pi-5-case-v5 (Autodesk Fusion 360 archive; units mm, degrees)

design "Pi 5 case" references "M3x5x4 heat-Insert"
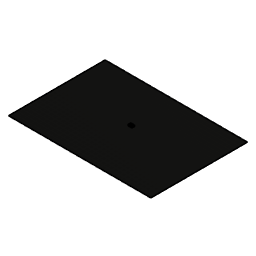
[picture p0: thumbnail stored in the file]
description: arrangementsContainer
description: STEP AP203
part number: RP-004882-DD - Pi 5 Mechanical Reference 3D model Iss1
description: Part Number
part number: PCB_for REF 060923
part number: GPIO Header for REF
part number: Micro HDMI for REF
part number: SD CARD for REF
part number: USB-C for REF
parameter "d2_1" = 180
parameter "d222_1" = 5
parameter "d223_1" = 5.3
parameter "d225_1" = 2
parameter "d226_1" = 10
parameter "d227_1" = 25
parameter "d228_1" = 20
parameter "d240_1" = 5
parameter "d241_1" = 5.3
parameter "d243_1" = 2
parameter "d244_1" = 10
parameter "d245_1" = 20
parameter "d246_1" = 25
parameter "d249_1" = 30
parameter "d250_1" = 0
parameter "d253_1" = 30
parameter "d254_1" = 0
parameter "d3" = 180
parameter "d4" = 0
parameter "d6" = 5
parameter "d7" = 5
parameter "d8" = 0
parameter "d10" = 24.193
parameter "d12" = 20.9455
parameter "d14" = 28.705
parameter "d16" = 27.166
parameter "d18" = 29.088
parameter "d20" = -25
parameter "d21" = 20.935
parameter "d23" = -3
parameter "d27" = 6
parameter "d28" = 0
parameter "d29" = 2
parameter "d30" = 2
parameter "d31" = 10
parameter "d32" = 2
parameter "d34" = 3
parameter "d35" = 20
parameter "d38" = 60
parameter "d39" = 0
parameter "d40" = -5
parameter "d42" = -3.933
parameter "d43" = -1
parameter "d44" = -3
parameter "d45" = 1
parameter "d46" = 1
parameter "d47" = 0
parameter "d48" = 5
parameter "d49" = -11.7
parameter "d51" = 3
parameter "d52" = -1.4
parameter "d53" = 3
parameter "d55" = 2
parameter "d56" = 1.4
parameter "d57" = -1
parameter "d58" = 1
parameter "d59" = -1
parameter "d60" = -0.4
parameter "d61" = -0.4
parameter "d62" = -1.053
parameter "d63" = -2
parameter "d65" = 0.172
parameter "d66" = -5
parameter "d67" = -2
parameter "d68" = -1
parameter "d69" = 2.5
parameter "d70" = -1
parameter "d71" = 0.4
parameter "d72" = 15
parameter "d74" = 0.1
parameter "d75" = 2
parameter "d76" = 0.75
parameter "d77" = 1
parameter "d79" = -1
parameter "d80" = 1
parameter "d83" = 0.75
parameter "d84" = 0.75
parameter "d85" = 0.8
parameter "d86" = 0.75
parameter "d87" = 0.75
parameter "d88" = 0.75
parameter "d89" = 0.75
parameter "d90" = 45 (= "Angle1")
parameter "d91" = 0 (= "Angle2")
parameter "d92" = 0.2
parameter "d93" = -0.2
parameter "d94" = -0.1
parameter "d95" = 2
parameter "d96" = 2
parameter "d97" = 15
parameter "d98" = 2
parameter "d101" = 0.6
parameter "d102" = 2.6
parameter "d103" = -0.1
parameter "d104" = 2
parameter "d105" = -0.1
parameter "d106" = -0.1
parameter "d107" = -0.1
parameter "d108" = 25
parameter "d109" = 2.6
parameter "d111" = 2.5
parameter "d112" = -0.1
parameter "d113" = 5
parameter "d114" = -3
parameter "d116" = 0.5
parameter "d117" = 7
parameter "d118" = 2
parameter "d119" = 5
parameter "d121" = -1
parameter "d122" = -2
parameter "d124" = 0.5
parameter "d128" = 2
parameter "d131" = 0.4
parameter "d132" = 0.5
parameter "d133" = 1
parameter "d134" = 3
parameter "d135" = 2.8
parameter "d137" = 3
parameter "d138" = 2.8
parameter "d140" = 7.375
parameter "d141" = 2
parameter "d143" = 2.8
parameter "d144" = 2.8
parameter "d145" = 5
parameter "d146" = 2.8
parameter "d147" = -0.4
parameter "d149" = -0.2
parameter "d151" = 0.4
parameter "d152" = 0.3
parameter "d153" = 0.4
parameter "d155" = -0.2
parameter "d156" = -0.2
parameter "d157" = 0.399
parameter "d159" = 5
parameter "d161" = 45 (= "Angle1")
parameter "d162" = 0 (= "Angle2")
parameter "d163" = 45 (= "Angle1")
parameter "d164" = 0 (= "Angle2")
parameter "d165" = 2.5
parameter "d166" = 3
parameter "d167" = 3
parameter "d168" = 2.5
parameter "d169" = 1
parameter "d170" = 1
parameter "d171" = 1
parameter "d172" = 3
parameter "d173" = 1
parameter "d174" = 1
parameter "d176" = 40.1
parameter "d177" = 40.1
parameter "d178" = -4.3752
parameter "d180" = 1.1
parameter "d181" = -4.3752
parameter "d183" = -0.1
parameter "d184" = 1
parameter "d185" = -2.291
parameter "d187" = 4
parameter "d188" = -1.625
parameter "d190" = 0
parameter "d191" = 10.23
parameter "d193" = 10
parameter "d194" = 2
parameter "d196" = 10
parameter "d197" = 2
parameter "d199" = 10
parameter "d200" = 2
parameter "d202" = 10
parameter "d203" = 2
parameter "d205" = 1
parameter "d206" = 0.4
parameter "d207" = 0.4
parameter "d208" = 8
parameter "d212" = 10
parameter "d213" = 3.3
parameter "d215" = -2
parameter "d217" = 0.5
parameter "d218" = 0.3
parameter "d219" = 0.3
parameter "d220" = 2
parameter "d221" = 3
parameter "d222" = 0.2
parameter "d224" = 0.5
parameter "d225" = 0.8
parameter "d226" = -0.8
parameter "d227" = 10
parameter "d229" = 2.5
parameter "d231" = 0.5
parameter "d232" = 2.5
parameter "d233" = 2
parameter "d238" = 5
parameter "d239" = -8
parameter "d241" = 0.5
parameter "d242" = -3.536
parameter "d243" = 3
parameter "d244" = 1
parameter "d246" = -50
parameter "d247" = 6.4
parameter "d248" = 2
parameter "d250" = 6.4
parameter "d251" = 2
parameter "d257" = 5
parameter "d258" = 0
parameter "d259" = 5
parameter "d260" = 3
parameter "d261" = -10.895
parameter "d262" = -4.25
parameter "d263" = 2
parameter "d267" = -35
parameter "d268" = 0
parameter "d269" = 0.3
parameter "d271" = 3
parameter "d283" = 2
parameter "d284" = 18
parameter "d285" = 135 (= "Angular Dimension-2")
parameter "d286" = 3
parameter "d287" = -5
parameter "d289" = 0.3
parameter "d292" = 35
parameter "d293" = 0
parameter "d294" = 0.3
parameter "d295" = 3
parameter "d296" = 3
parameter "d297" = 2
parameter "d299" = 1.5
parameter "d300" = 3
parameter "d301" = 3
parameter "d302" = 5
parameter "d303" = 0
parameter "d304" = 0
parameter "d305" = 2
parameter "d306" = 0
parameter "d307" = 0
parameter "d308" = 2
parameter "d309" = 0
parameter "d310" = 0
parameter "d311" = 0
parameter "d312" = -2
parameter "d313" = 0
parameter "d314" = -2
parameter "d315" = 0
parameter "d316" = 0
parameter "d317" = -2.002
parameter "d319" = 0.1
parameter "d320" = 2.6
parameter "d322" = 0.1
parameter "d323" = 11.8
parameter "d325" = 4.883
parameter "d326" = -4.2
parameter "d328" = 1
parameter "d330" = 0
parameter "d331" = -0.805
parameter "d332" = -5
parameter "d333" = -9
parameter "d334" = 0
parameter "d335" = 0
parameter "d336" = 0
parameter "d337" = 1
parameter "d338" = 0
parameter "d339" = 0.75
parameter "d340" = 15
parameter "d341" = 5
parameter "d342" = 1
parameter "d345" = 41.4
parameter "d347" = -9
parameter "d348" = 6.5
parameter "d349" = 2.1
parameter "d351" = 1
parameter "d352" = 1
parameter "d353" = 0.4
parameter "d355" = 0.4
parameter "d357" = 2.8
parameter "d359" = -40
parameter "d361" = -18.9
parameter "d363" = 0.75
parameter "d365" = 15
parameter "d366" = 2
parameter "d367" = 3
parameter "d369" = 3
parameter "d370" = 1.9
parameter "d371" = 1.9
parameter "d372" = 1.883
parameter "d374" = 0.5
parameter "d375" = 1
parameter "d376" = 4
parameter "d381" = 3
parameter "d383" = 3
parameter "d384" = -5
parameter "d385" = 3
parameter "d386" = 3
parameter "d389" = 5
parameter "d390" = 5
parameter "d393" = 20
parameter "d396" = 5
parameter "d397" = -5
parameter "d398" = 2
parameter "d399" = 2
parameter "d401" = 9.14
parameter "d402" = 5
parameter "d404" = 3
parameter "d405" = 2.8
parameter "d407" = 0
parameter "d408" = 0
parameter "d409" = -1
parameter "d410" = 2
parameter "d411" = 2.5
parameter "d412" = -0.5
parameter "d413" = -0.1
parameter "d414" = 0.5
parameter "d415" = 20
parameter "d416" = 135 (= "Angular Dimension-2")
parameter "d417" = -6
parameter "d419" = -1
parameter "d420" = -5.171
parameter "d422" = 0 (= "-4.680E-05 mm")
parameter "d423" = 0 (= "-4.680E-05 mm")
parameter "d424" = -6
parameter "d426" = 0.5
parameter "d427" = -0.1
parameter "d428" = 1
parameter "d430" = 22.5 (= "Angle1")
parameter "d431" = 0 (= "Angle2")
parameter "d432" = 1
parameter "d433" = 1
parameter "d434" = 0.8
parameter "d435" = 0.4
parameter "d436" = 0.4
parameter "d437" = 5
parameter "d438" = 5
parameter "d439" = 3
parameter "d440" = 3
parameter "d441" = 35
parameter "d442" = 35
parameter "d443" = 45 (= "Angular Dimension-2")
parameter "d444" = 45 (= "Angular Dimension-3")
parameter "d445" = 3
parameter "d447" = 5
parameter "d448" = 2.8
parameter "d450" = 5
parameter "d451" = 2.8
parameter "d453" = 0.2
parameter "d454" = -0.1
parameter "d455" = -0.1
parameter "d456" = -0.1
parameter "d458" = 12
parameter "d459" = 8
parameter "d460" = 2.8
parameter "d462" = 0
parameter "d463" = 8
parameter "d464" = 5
parameter "d466" = 0.3
parameter "d467" = 0.25
parameter "d468" = 0.15
parameter "d469" = 0.5
parameter "d470" = 37
parameter "d471" = 2
parameter "d472" = 3
parameter "d473" = 8
parameter "d474" = -8
parameter "d478" = -30
parameter "d479" = 0
parameter "d480" = 0.3
parameter "d481" = 7
parameter "d482" = 7
parameter "d483" = 2
parameter "d485" = 1.9
parameter "d486" = 0.5
parameter "d487" = 2
parameter "d488" = 3
parameter "d489" = 60
parameter "d490" = 5
parameter "d491" = -5
parameter "d493" = 5
parameter "d494" = 1.4
parameter "d495" = -1
parameter "d496" = 7
parameter "d497" = 2
parameter "d499" = 7
parameter "d500" = 2
parameter "d502" = 5
parameter "d505" = 0
parameter "d506" = 30
parameter "d507" = -2
parameter "d509" = 0.3
parameter "d510" = 0.3
parameter "d511" = 2
parameter "d512" = 2
parameter "d513" = -2.4
parameter "d514" = -2
parameter "d516" = 2
parameter "d517" = -0.1
parameter "d518" = 0.75
parameter "d519" = 2
parameter "d520" = 1.581
parameter "d521" = 1.369
parameter "d522" = 0
parameter "d523" = -2
parameter "d525" = 8.308
named bodies: "Pi5_mount", "BOTTOM (1) (1)", "FRONT", "TOP", "base"

design "M3x5x4 heat-Insert"
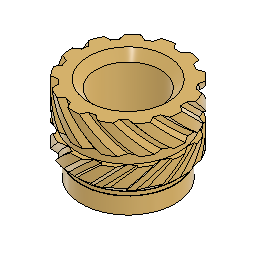
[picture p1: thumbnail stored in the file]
